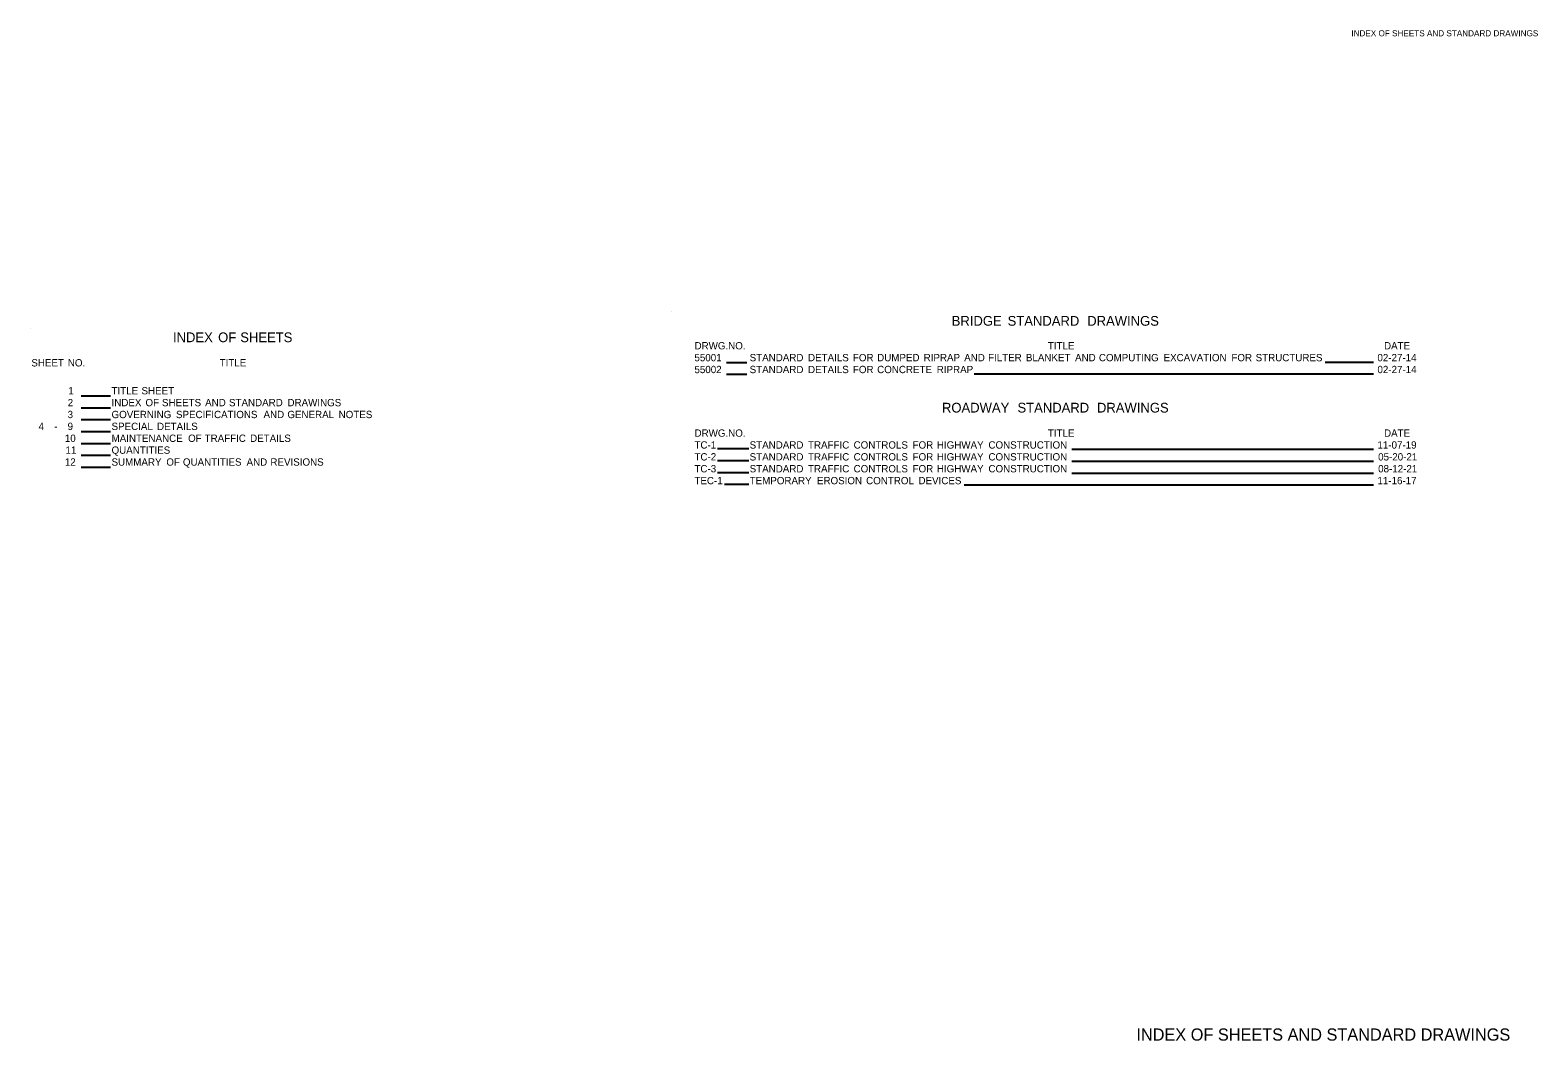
# Model space of a CAD drawing. Extents: x 163 to 1648, y 38 to 1033.
import ezdxf

# ---------------------------------------------------------------- set-up
doc = ezdxf.new("R2010")
doc.units = 0
for name, color, linetype in [('Default', 7, 'Continuous'), ('R_Logo', 7, 'Continuous'), ('STAMP_BOL', 7, 'Continuous')]:
    doc.layers.add(name, color=color, linetype=linetype)

msp = doc.modelspace()

# ---------------------------------------------------------------- linework, layer by layer
at = {"layer": 'Default'}
for p, q in [((849, 705.6), (869, 705.6)), ((1438.4, 706), (1486.2, 706)), ((849, 694), (869, 694)), ((1092.9, 694.4), (1486.2, 694.4)), ((213.3, 672.7), (242, 672.7)), ((213.3, 661), (242, 661)), ((213.3, 649.3), (242, 649.3)), ((213.3, 637.6), (242, 637.6)), ((213.3, 625.9), (242, 625.9)), ((213.3, 614.2), (242, 614.2)), ((840.1, 620.8), (870.8, 620.8)), ((840.1, 609.1), (870.8, 609.1)), ((1188.9, 620.1), (1486.2, 620.1)), ((213.3, 602.5), (242, 602.5)), ((840.1, 597.4), (870.8, 597.4)), ((1188.9, 608.4), (1486.2, 608.4)), ((1188.9, 596.7), (1486.2, 596.7)), ((846.8, 585.7), (870.8, 585.7)), ((1083, 585), (1486.2, 585))]:
    msp.add_line(p, q, dxfattribs=at)
at = {"layer": 'STAMP_BOL'}
for p, q in [((794.5, 755.6), (794.5, 755.6)), ((163, 739.4), (163, 739.4))]:
    msp.add_line(p, q, dxfattribs=at)

# ---------------------------------------------------------------- texts
at = {"layer": 'Default'}
for s, height, p in [('BRIDGE', 9.6, (1070.7, 741.8)), (' STANDARD', 9.6, (1122.2, 741.8)), (' DRAWINGS', 9.6, (1200.6, 741.8)), ('INDEX', 9.6, (303.7, 725.6)), (' OF', 9.6, (344.6, 725.6)), (' SHEETS', 9.6, (366.4, 725.6)), ('55001', 7.2, (817.3, 706.8)), ('DRWG.NO.', 7.2, (817.4, 718.5)), ('STANDARD', 7.2, (871.7, 706.8)), (' DETAILS', 7.2, (926.5, 706.8)), (' FOR', 7.2, (970.7, 706.8)), (' DUMPED', 7.2, (994.6, 706.8)), (' RIPRAP', 7.2, (1040.4, 706.8)), (' AND', 7.2, (1080.3, 706.8)), (' FILTER', 7.2, (1103.8, 706.8)), (' BLANKET', 7.2, (1141.1, 706.8)), ('TITLE', 7.2, (1165.4, 718.5)), (' AND', 7.2, (1189.5, 706.8)), (' COMPUTING', 7.2, (1213, 706.8)), (' EXCAVATION', 7.2, (1276.7, 706.8)), (' FOR', 7.2, (1343.5, 706.8)), (' STRUCTURES', 7.2, (1367.4, 706.8)), ('02-27-14', 7.2, (1490, 706.8)), ('DATE', 7.2, (1496.5, 718.5)), ('SHEET', 7.2, (164.2, 701.7)), (' NO.', 7.2, (197.5, 701.7)), ('TITLE', 7.2, (349.7, 701.7)), ('55002', 7.2, (817.3, 695.1)), ('STANDARD', 7.2, (871.7, 695.1)), (' DETAILS', 7.2, (926.5, 695.1)), (' FOR', 7.2, (970.7, 695.1)), (' CONCRETE', 7.2, (994.6, 695.1)), (' RIPRAP', 7.2, (1053.3, 695.1)), ('02-27-14', 7.2, (1490, 695.1)), ('2', 7.2, (200, 662.5)), ('1', 7.2, (200.6, 674.2)), ('TITLE', 7.2, (243.2, 674.2)), ('INDEX', 7.2, (243.2, 662.5)), (' SHEET', 7.2, (270, 674.2)), (' OF', 7.2, (273.9, 662.5)), (' SHEETS', 7.2, (290.2, 662.5)), (' AND', 7.2, (332.7, 662.5)), (' STANDARD', 7.2, (356.2, 662.5)), (' DRAWINGS', 7.2, (413.8, 662.5)), ('3', 7.2, (199.9, 650.8)), ('GOVERNING', 7.2, (243.2, 650.8)), (' SPECIFICATIONS', 7.2, (304, 650.8)), (' AND', 7.2, (390.2, 650.8)), (' GENERAL', 7.2, (413.7, 650.8)), (' NOTES', 7.2, (464.2, 650.8)), ('ROADWAY', 9.6, (1061.1, 656.3)), (' STANDARD', 9.6, (1131.9, 656.3)), (' DRAWINGS', 9.6, (1210.2, 656.3)), ('4', 7.2, (171.3, 639.1)), ('-', 7.2, (186.7, 639.1)), ('9', 7.2, (199.9, 639.1)), ('SPECIAL', 7.2, (243.2, 639.1)), (' DETAILS', 7.2, (285.3, 639.1)), ('DRWG.NO.', 7.2, (817.4, 632.5)), ('TITLE', 7.2, (1165.4, 632.5)), ('DATE', 7.2, (1496.5, 632.5)), ('10', 7.2, (197.2, 627.4)), ('MAINTENANCE', 7.2, (243.2, 627.4)), (' OF', 7.2, (315.9, 627.4)), (' TRAFFIC', 7.2, (332.2, 627.4)), (' DETAILS', 7.2, (377, 627.4)), ('TC-1', 7.2, (817.3, 620.8)), ('STANDARD', 7.2, (871.7, 620.8)), (' TRAFFIC', 7.2, (926.5, 620.8)), (' CONTROLS', 7.2, (971.4, 620.8)), (' FOR', 7.2, (1029.5, 620.8)), (' HIGHWAY', 7.2, (1053.4, 620.8)), (' CONSTRUCTION', 7.2, (1104.2, 620.8)), ('11-07-19', 7.2, (1490, 620.8)), ('12', 7.2, (197.2, 604)), ('11', 7.2, (197.8, 615.7)), ('QUANTITIES', 7.2, (243.2, 615.7)), ('SUMMARY', 7.2, (243.2, 604)), (' OF', 7.2, (294.5, 604)), (' QUANTITIES', 7.2, (310.8, 604)), (' AND', 7.2, (373.5, 604)), (' REVISIONS', 7.2, (397, 604)), ('TC-2', 7.2, (817.3, 609.1)), ('STANDARD', 7.2, (871.7, 609.1)), (' TRAFFIC', 7.2, (926.5, 609.1)), (' CONTROLS', 7.2, (971.4, 609.1)), (' FOR', 7.2, (1029.5, 609.1)), (' HIGHWAY', 7.2, (1053.4, 609.1)), (' CONSTRUCTION', 7.2, (1104.2, 609.1)), ('05-20-21', 7.2, (1490.7, 609.1)), ('TC-3', 7.2, (817.3, 597.4)), ('STANDARD', 7.2, (871.7, 597.4)), (' TRAFFIC', 7.2, (926.5, 597.4)), (' CONTROLS', 7.2, (971.4, 597.4)), (' FOR', 7.2, (1029.5, 597.4)), (' HIGHWAY', 7.2, (1053.4, 597.4)), (' CONSTRUCTION', 7.2, (1104.2, 597.4)), ('08-12-21', 7.2, (1490.7, 597.4)), ('TEC-1', 7.2, (817.3, 585.7)), ('TEMPORARY', 7.2, (871.7, 585.7)), (' EROSION', 7.2, (935.3, 585.7)), (' CONTROL', 7.2, (983.7, 585.7)), (' DEVICES', 7.2, (1035.3, 585.7)), ('11-16-17', 7.2, (1490, 585.7))]:
    msp.add_text(s, height=height, dxfattribs=at).set_placement(p)
at = {"layer": 'R_Logo'}
msp.add_text('INDEX OF SHEETS AND STANDARD DRAWINGS', height=6, dxfattribs=at).set_placement((1464.3, 1026.8))
at = {"layer": 'STAMP_BOL'}
msp.add_text('INDEX OF SHEETS AND STANDARD DRAWINGS', height=12, dxfattribs=at).set_placement((1252.6, 37.8))

doc.saveas('drawing.dxf')
